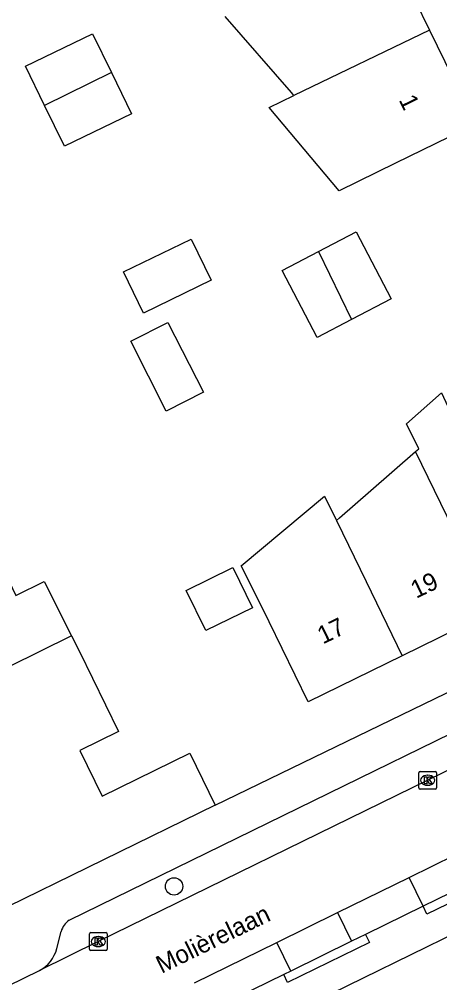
# Model space of a CAD drawing. Extents: x 160457 to 162082, y 388340 to 389736.
# Drawn here: x 160813.2 to 160836.8, y 388727.5 to 388781.6 of the extents above; entities that cross this region are included whole.
import ezdxf

# ---------------------------------------------------------------- set-up
doc = ezdxf.new("R2010")
doc.units = 0
for name, color, linetype in [('IMGEO_Boom', 7, 'Continuous'), ('IMGEO_Kolk', 7, 'Continuous'), ('IMGEO_Openbare_ruimte_label', 7, 'Continuous'), ('IMGEO_Pand', 7, 'Continuous'), ('IMGEO_Pand_nummerreeks', 7, 'Continuous'), ('IMGEO_Parkeervlak_open', 7, 'Continuous'), ('IMGEO_Rijbaan_lokaal_gesloten', 7, 'Continuous'), ('IMGEO_Voetpad_open', 7, 'Continuous')]:
    doc.layers.add(name, color=color, linetype=linetype)

msp = doc.modelspace()

# ---------------------------------------------------------------- linework, layer by layer
at = {"layer": 'IMGEO_Boom'}
msp.add_circle((160821.902, 388732.885), 0.489, dxfattribs=at)
at = {"layer": 'IMGEO_Kolk'}
for p, q in [((160835.656, 388738.42), (160835.656, 388739.272)), ((160835.731, 388739.346), (160836.583, 388739.346)), ((160836.144, 388739.126), (160836.169, 388739.126)), ((160836.657, 388739.272), (160836.657, 388738.42)), ((160836.167, 388738.566), (160836.142, 388738.566)), ((160836.583, 388738.346), (160835.731, 388738.346)), ((160817.146, 388729.362), (160817.146, 388730.214)), ((160817.221, 388730.288), (160818.073, 388730.288)), ((160817.634, 388730.068), (160817.659, 388730.068)), ((160818.147, 388730.214), (160818.147, 388729.362)), ((160818.073, 388729.288), (160817.221, 388729.288)), ((160817.657, 388729.508), (160817.632, 388729.508))]:
    msp.add_line(p, q, dxfattribs=at)
for points in [[(160835.656, 388738.42), (160835.656, 388739.272)], [(160835.731, 388739.346), (160836.583, 388739.346)], [(160835.977, 388739.046), (160836.1, 388739.046), (160836.1, 388738.895), (160836.23, 388739.046), (160836.394, 388739.046), (160836.248, 388738.895), (160836.401, 388738.646), (160836.249, 388738.646), (160836.164, 388738.81), (160836.1, 388738.743), (160836.1, 388738.646), (160835.977, 388738.646), (160835.977, 388739.046)], [(160836.657, 388739.272), (160836.657, 388738.42)], [(160836.583, 388738.346), (160835.731, 388738.346)], [(160817.146, 388729.362), (160817.146, 388730.214)], [(160817.221, 388730.288), (160818.073, 388730.288)], [(160817.467, 388729.988), (160817.59, 388729.988), (160817.59, 388729.837), (160817.72, 388729.988), (160817.884, 388729.988), (160817.738, 388729.837), (160817.891, 388729.588), (160817.739, 388729.588), (160817.654, 388729.752), (160817.59, 388729.685), (160817.59, 388729.588), (160817.467, 388729.588), (160817.467, 388729.988)], [(160818.147, 388730.214), (160818.147, 388729.362)], [(160818.073, 388729.288), (160817.221, 388729.288)]]:
    msp.add_lwpolyline(points, dxfattribs=at)
for centre, start, end in [((160835.733, 388739.27), 91.552, 178.448), ((160835.733, 388739.27), 91.552, 178.448), ((160836.581, 388739.27), 1.552, 88.448), ((160836.581, 388739.27), 1.552, 88.448), ((160835.733, 388738.422), 181.552, 268.448), ((160835.733, 388738.422), 181.552, 268.448), ((160836.581, 388738.422), 271.552, 358.448), ((160836.581, 388738.422), 271.552, 358.448), ((160817.223, 388730.212), 91.552, 178.448), ((160817.223, 388730.212), 91.552, 178.448), ((160818.071, 388730.212), 1.552, 88.448), ((160818.071, 388730.212), 1.552, 88.448), ((160817.223, 388729.364), 181.552, 268.448), ((160817.223, 388729.364), 181.552, 268.448), ((160818.071, 388729.364), 271.552, 358.448), ((160818.071, 388729.364), 271.552, 358.448)]:
    msp.add_arc(centre, 0.0765, start, end, dxfattribs=at)
for centre, major_axis, ratio, start_param, end_param in [((160836.143, 388738.846), (-0.387, 0.002), 0.722429, 4.712389, 7.853982), ((160836.168, 388738.846), (-0.39, 0.002), 0.717154, 1.570796, 4.712389), ((160817.633, 388729.788), (-0.387, 0.002), 0.722429, 4.712389, 7.853982), ((160817.658, 388729.788), (-0.39, 0.002), 0.717154, 1.570796, 4.712389)]:
    msp.add_ellipse(centre, major_axis=major_axis, ratio=ratio, start_param=start_param, end_param=end_param, dxfattribs=at)
at = {"layer": 'IMGEO_Pand'}
for points in [[(160832.364, 388785.473), (160833.733, 388786.147), (160836.254, 388780.978)], [(160828.638, 388777.3), (160828.495, 388777.464), (160824.774, 388781.733)], [(160814.629, 388776.735), (160813.558, 388778.942), (160817.322, 388780.769), (160818.382, 388778.584)], [(160836.254, 388780.978), (160838.836, 388775.684), (160834.342, 388773.493), (160831.187, 388771.955), (160827.255, 388776.632), (160828.638, 388777.3)], [(160836.254, 388780.978), (160828.638, 388777.3)], [(160818.382, 388778.584), (160819.502, 388776.276), (160815.738, 388774.45), (160814.629, 388776.735)], [(160818.382, 388778.584), (160814.629, 388776.735)], [(160830.018, 388768.538), (160832.139, 388769.646), (160834.103, 388765.887), (160831.873, 388764.722)], [(160822.871, 388769.24), (160823.995, 388766.928), (160820.182, 388765.084), (160819.059, 388767.396), (160822.871, 388769.24)], [(160831.873, 388764.722), (160829.938, 388763.711), (160827.97, 388767.467), (160830.018, 388768.538)], [(160830.018, 388768.538), (160831.873, 388764.722)], [(160819.478, 388763.496), (160821.559, 388764.553), (160823.549, 388760.635), (160821.468, 388759.578), (160819.478, 388763.496)], [(160835.476, 388757.311), (160835.65, 388757.462), (160834.969, 388758.854), (160836.927, 388760.605), (160838.235, 388757.784), (160840.593, 388759.815), (160841.258, 388758.447)], [(160831.024, 388753.438), (160831.201, 388753.592), (160832.962, 388755.124), (160835.476, 388757.311)], [(160839.837, 388748.341), (160839.03, 388750), (160835.476, 388757.311)], [(160834.719, 388745.838), (160829.439, 388743.256), (160827.243, 388747.747), (160826.125, 388750), (160825.683, 388750.891), (160830.357, 388754.809), (160831.024, 388753.438)], [(160810.586, 388754.187), (160812.636, 388750), (160813.015, 388749.225), (160814.601, 388750), (160816.146, 388746.949)], [(160831.024, 388753.438), (160832.696, 388750), (160834.719, 388745.838)], [(160823.69, 388747.247), (160822.585, 388749.506), (160825.214, 388750.792), (160826.318, 388748.533), (160823.69, 388747.247)], [(160839.837, 388748.341), (160834.719, 388745.838)], [(160816.146, 388746.949), (160809.121, 388743.502), (160806.444, 388742.188)], [(160816.146, 388746.949), (160816.586, 388746.08), (160818.784, 388741.588), (160816.607, 388740.523), (160817.865, 388737.953), (160822.79, 388740.359), (160824.212, 388737.448)], [(160824.212, 388737.448), (160811.637, 388731.307)]]:
    msp.add_lwpolyline(points, dxfattribs=at)
at = {"layer": 'IMGEO_Parkeervlak_open'}
for points in [[(160835.895, 388731.782), (160835.109, 388733.382)], [(160831.094, 388731.411), (160831.884, 388729.803)], [(160828.469, 388728.132), (160827.682, 388729.736)]]:
    msp.add_lwpolyline(points, dxfattribs=at)
at = {"layer": 'IMGEO_Rijbaan_lokaal_gesloten'}
for points in [[(160856.45, 388748.792), (160853.191, 388747.155), (160836.158, 388738.845), (160817.647, 388729.787), (160814.348, 388728.165)], [(160835.109, 388733.382), (160837.704, 388734.656), (160838.835, 388735.21)], [(160831.094, 388731.411), (160835.109, 388733.382)], [(160827.682, 388729.736), (160831.094, 388731.411)], [(160823.061, 388727.467), (160827.682, 388729.736)], [(160810.77, 388726.43), (160814.348, 388728.165)]]:
    msp.add_lwpolyline(points, dxfattribs=at)
at = {"layer": 'IMGEO_Voetpad_open'}
for points in [[(160929.117, 388774.962), (160878.066, 388750), (160811.085, 388717.249)], [(160824.212, 388737.448), (160850.145, 388750), (160855.113, 388752.423)], [(160816.007, 388730.993), (160852.935, 388749.039)], [(160840.529, 388734.025), (160840.746, 388733.575), (160836.112, 388731.332), (160835.895, 388731.782)], [(160839.629, 388733.589), (160835.895, 388731.782)], [(160835.895, 388731.782), (160832.668, 388730.187)], [(160815.315, 388729.393), (160815.553, 388730.352)], [(160832.668, 388730.187), (160832.887, 388729.738), (160828.282, 388727.484), (160828.063, 388727.933)], [(160831.884, 388729.803), (160828.469, 388728.132)], [(160832.668, 388730.187), (160831.884, 388729.803)], [(160828.063, 388727.933), (160824.549, 388726.213)], [(160828.469, 388728.132), (160828.063, 388727.933)]]:
    msp.add_lwpolyline(points, dxfattribs=at)
for centre, radius, start, end in [((160816.723, 388730.005), 1.22, 125.9179, 163.4647), ((160813.441, 388729.874), 1.935, 297.9593, 345.6027)]:
    msp.add_arc(centre, radius, start, end, dxfattribs=at)

# ---------------------------------------------------------------- texts
at = {"layer": 'IMGEO_Openbare_ruimte_label'}
msp.add_text('Molièrelaan', height=1, rotation=25.9757, dxfattribs=at).set_placement((160821.198, 388727.971))
at = {"layer": 'IMGEO_Pand_nummerreeks'}
for s, rotation, p in [('1', 296.0006, (160834.518, 388777.054)), ('19', 26.0639, (160835.512, 388749.032)), ('17', 26.0581, (160830.27, 388746.468))]:
    msp.add_text(s, height=1, rotation=rotation, dxfattribs=at).set_placement(p)

doc.saveas('drawing.dxf')
